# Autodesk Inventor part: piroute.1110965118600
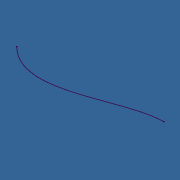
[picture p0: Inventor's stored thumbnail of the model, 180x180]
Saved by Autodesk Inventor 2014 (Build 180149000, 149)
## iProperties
TPVersion: 11.0.2
Company: Autodesk, Inc.
StyleName: _Piping Style 23
Created: 2005-03
Part Number: piroute.1110965118600
Document SubType Name: Tube & Pipe
Designer: Autodesk, Inc.
Density: 1 g/cm^3
Material: Generic
Appearance: Default
ActiveState: True
Angle: UnInitValue
BendRadius: 0.500 in
CouplingKey: UnInitValue
DefaultBendRadius: UnInitValue
Diameter: 1/2
DiameterType: Nominal
Elbow45Key: UnInitValue
Elbow90Key: UnInitValue
ElbowCustomKey: UnInitValue
EndFittingKey: v3#b50cb43e-68c0-48ac-8e25-7ef224ce0e6c#3
Ending: UnInitValue
FittingMaterial: UnInitValue
FittingStandard: UnInitValue
FlangeKey: UnInitValue
Gap: UnInitValue
GasketKey: UnInitValue
ID: 0.500 in
IsButtWelded: UnInitValue
IsFlanged: UnInitValue
IsSelfDraining: UnInitValue
Material: UnInitValue
MixedUnits: UnInitValue
Name: Hydraulic Hose - Male Straight Thread
OD: 0.880 in
PipeKey: v3#d489867e-ac9b-47ea-b952-0a1b885f66be#4
PipeType: Flexible Hose
PipingComponentColor: As Material
RoundUpValue: 0.125 in
RouteDirection45: UnInitValue
RouteDirection90: UnInitValue
Schedule: ID=0.5
ShowGap: UnInitValue
Standard: UnInitValue
StartFittingKey: v3#b50cb43e-68c0-48ac-8e25-7ef224ce0e6c#3
SuppressEndFitting: False
SuppressStartFitting: False
UseFlangsForCouplings: UnInitValue
UseSubASM: True
_ComponentInfo: <CS><C N="Pipe" R="1.117600" OR="1.117600" IR="0.635000" PL="PL" PartType="pipe" SymKey="" PN="Parker Hydraulic Hose - No Skive 1/2"><CO N="1"><FE V="0"/><FD V=
Author: Autodesk, Inc.
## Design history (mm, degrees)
workpoint "Work Point1"
workpoint "Work Point2"
workplane "Work Plane1"
workplane "Work Plane2"
sketch "3D Sketch1" dims "d0" = 10, "d1" = 10, "d2" = -0.01 (derived), "d3" = -0.01 (derived)
other parameters: "B" = 12.7 [user parameter]
